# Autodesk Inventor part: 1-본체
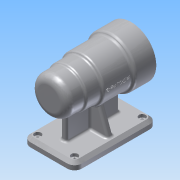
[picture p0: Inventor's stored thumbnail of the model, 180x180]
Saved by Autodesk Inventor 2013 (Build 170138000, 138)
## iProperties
Created: 2016-06
Part Number: 1-본체
Material: 알루미늄 6061
Document SubType Name: Modeling
Designer: Administrator
Density: 2.71 g/cm^3
Mass: 674.634 g
Surface Area: 646.752 cm^2
Volume: 248.942 cm^3
Author: Administrator
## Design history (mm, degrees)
sketch "스케치1"
  geometry: C1 r 25 at (0, 0); 1 further point
  constraints: 1 centre point, 1 coincident
  dimensions: "d0" = 50 diameter of C1
extrude "돌출1" new body sketch "스케치1" distance "d2" = 25; taper "d3" = 0 deg
sketch "스케치2"
  geometry: C1 r 25 at (0, 0) reference; C2 r 27 at (0, 0)
  constraints: 1 centre point, 1 coincident
  dimensions: "d4" = 54 diameter of C2
extrude "돌출2" join sketch "스케치2" distance "d6" = 20; taper "d7" = 0 deg
sketch "스케치3"
  geometry: C1 r 27 at (0, 0) reference; C2 r 30 at (0, 0)
  constraints: 1 centre point, 1 coincident
  dimensions: "d8" = 60 diameter of C2
extrude "돌출3" join sketch "스케치3" distance "d10" = 39; taper "d11" = 0 deg
sketch "스케치4"
  geometry: C1 r 30 at (0, 0) reference; C2 r 34 at (0, 0)
  constraints: 1 centre point, 1 coincident
  dimensions: "d12" = 68 diameter of C2
extrude "돌출4" join sketch "스케치4" distance "d14" = 28; taper "d15" = 0 deg
node "작업 평면1"
sketch "스케치5"
  geometry: L1 (-35, 25)-(35, 25); L2 (35, 25)-(35, -87); L3 (35, -87)-(-35, -87); L4 (-35, -87)-(-35, 25); L5 (25, 25)-(-25, 25) reference; L6 (-34, -87)-(34, -87) reference; 3 further points
  constraints: 8 end point, 2 midpoint, 2 parallel, 1 coincident, 1 horizontal, 1 horizontal alignment, 1 perpendicular
  dimensions: "d17" = 112 distance of L1.end L2.end; "d19" = 70 distance of L1.start L1.end
extrude "돌출5" join sketch "스케치5" distance "d20" = 10; taper "d21" = 0 deg
sketch "스케치6"
  geometry: L1 (-35, -25)-(35, -25) reference; L2 (35, 87)-(-35, 87) reference; L3 (-35, 87)-(-35, -25) reference; L4 (-4, -5)-(4, -5); L5 (4, -5)-(4, 67); L6 (4, 67)-(-4, 67); L7 (-4, 67)-(-4, -5); 5 further points
  constraints: 8 end point, 4 midpoint, 2 parallel, 1 horizontal, 1 horizontal alignment, 1 perpendicular, 1 vertical alignment
  dimensions: "d22" = 8 distance between parallel lines of L5 L7; "d24" = 20 distance between parallel lines of L2 L6
extrude "돌출6" join sketch "스케치6" stored distance "d25" = 10; taper "d26" = 0 deg
node "작업 평면2"
sketch "스케치7"
  geometry: L1 (39, 0)-(-31, 0) reference; L2 (-24, 0)-(-11.509, 34.32); L3 (-31, -10)-(-31, 0) reference; A1 r 30 centre (4, 60) between (8, 30.268) and (0, 30.268) reference; 1 further point
  constraints: 2 end point, 1 point on circle, 1 point on line
  dimensions: "d27" = 7 distance from line of L3 L2.start; "d29" = 110 deg angle of L2 L1
feature "리브1" sketch "스케치7" dims "d30" = 1, "d31" = 8, "d32" = 0, "d33" = 0, "d34" = 1, "d35" = 1
sketch "스케치8"
  geometry: L1 (39, 0)-(-31, 0) reference; L2 (32, 0)-(19.509, 34.32); L3 (39, -10)-(39, 0) reference; A1 r 30 centre (4, 60) between (8, 30.268) and (0, 30.268) reference; 1 further point
  constraints: 2 end point, 1 point on circle, 1 point on line
  dimensions: "d36" = 7 distance from line of L3 L2.start; "d37" = 110 deg angle of L1 L2
feature "리브2" sketch "스케치8" dims "d38" = 1, "d39" = 8, "d40" = 0, "d41" = 0, "d42" = 1, "d43" = 1
sketch "스케치9"
  geometry: C1 r 34 at (0, 0) reference; C2 r 21 at (0, 0)
  constraints: 1 centre point, 1 coincident
  dimensions: "d44" = 42 diameter of C2
extrude "돌출7" cut sketch "스케치9" distance "d46" = 15; taper "d47" = 0 deg
sketch "스케치10"
  geometry: C1 r 21 at (0, 0) reference; C2 r 24 at (0, 0)
  constraints: 1 centre point, 1 coincident
  dimensions: "d48" = 48 diameter of C2
extrude "돌출8" cut sketch "스케치10" distance "d50" = 54; taper "d51" = 0 deg
sketch "스케치11"
  geometry: C1 r 24 at (0, 0) reference; C2 r 21 at (0, 0)
  constraints: 1 centre point, 1 coincident
  dimensions: "d52" = 42 diameter of C2
extrude "돌출9" cut sketch "스케치11" distance "d54" = 12; taper "d55" = 0 deg
sketch "스케치12"
  geometry: C1 r 21 at (0, 0) reference; C2 r 17.5 at (0, 0)
  constraints: 1 centre point, 1 coincident
  dimensions: "d56" = 35 diameter of C2
extrude "돌출10" cut sketch "스케치12" distance "d58" = 18; taper "d59" = 0 deg
sketch "스케치13"
  geometry: C1 r 17.5 at (0, 0) reference; C2 r 16 at (0, 0)
  constraints: 1 centre point, 1 coincident
  dimensions: "d60" = 32 diameter of C2
extrude "돌출11" cut sketch "스케치13" distance "d62" = 4; taper "d63" = 0 deg
sketch "스케치14"
  geometry: C1 r 16 at (0, 0) reference; C2 r 10.5 at (0, 0)
  constraints: 1 centre point, 1 coincident
  dimensions: "d64" = 21 diameter of C2
extrude "돌출12" cut sketch "스케치14" distance "d66" = 3; taper "d67" = 0 deg
fillet "모깎기1" dims "d68" = 10
fillet "모깎기2" dims "d69" = 3
fillet "모깎기3" dims "d70" = 3
fillet "모깎기4" dims "d71" = 10
chamfer "모따기1" distance "d72" = 4; stored, may be unused: second distance "d73" = 2, angle "d74" = 45 deg
sketch "스케치15"
  geometry: L1 (-31, -15)-(-31, 77) reference; L2 (25, -21)-(-25, -21) reference; C1 r 4.5 at (-25, -15); C2 r 4.5 at (25, -15); C3 r 4.5 at (-25, 77); C4 r 4.5 at (25, 77); 3 further points
  constraints: 4 centre point, 3 equal radius, 2 horizontal alignment, 2 midpoint, 2 vertical alignment
  dimensions: "d75" = 92 distance of C1.centre C3.centre; "d77" = 46 vertical distance of point (-31, 31) C3.centre; "d78" = 50 distance of C2.centre C1.centre; "d79" = 25 horizontal distance of point (0, -21) C2.centre; "d80" = 9 diameter of C3
extrude "돌출13" cut sketch "스케치15" distance "d81" = 4; taper "d82" = 0 deg
sketch "스케치16"
  geometry: C1 r 4.5 at (0, 0) reference; C2 r 2.5 at (0, 0); 1 further point
  constraints: 1 centre point, 1 coincident
  dimensions: "d83" = 5 diameter of C2
extrude "돌출14" cut sketch "스케치16" stored distance "d85" = 4; taper "d86" = 0 deg
sketch "스케치17"
  geometry: C1 r 4.5 at (0, 0) reference; C2 r 2.5 at (0, 0); 1 further point
  constraints: 1 centre point, 1 coincident
  dimensions: "d87" = 5 diameter of C2
extrude "돌출15" cut sketch "스케치17" distance "d89" = 7; taper "d90" = 0 deg
sketch "스케치18"
  geometry: C1 r 4.5 at (0, 0) reference; C2 r 2.5 at (0, 0); 1 further point
  constraints: 1 centre point, 1 coincident
  dimensions: "d91" = 5 diameter of C2
extrude "돌출16" cut sketch "스케치18" distance "d93" = 7; taper "d94" = 0 deg
sketch "스케치19"
  geometry: C1 r 4.5 at (0, 0) reference; C2 r 2.5 at (0, 0); 1 further point
  constraints: 1 centre point, 1 coincident
  dimensions: "d95" = 5 diameter of C2
extrude "돌출17" cut sketch "스케치19" distance "d97" = 7; taper "d98" = 0 deg
fillet "모깎기5" dims "d99" = 3
fillet "모깎기6" dims "d100" = 0.3
fillet "모깎기7" dims "d101" = 3
chamfer "모따기2" distance "d102" = 1; stored, may be unused: second distance "d103" = 2, angle "d104" = 45 deg
sketch "스케치20"
  geometry: C1 r 34 at (0, 0) reference; C2 r 22 at (0, 0) reference; A1 r 26 centre (0, 0) between (0, 26) and (-26, 0); 2 further points
  constraints: 4 point on circle, 2 horizontal alignment, 2 vertical alignment, 1 centre point, 1 coincident
  dimensions: "d105" = 52 diameter of A1
hole "구멍1" sketch "스케치20" at (0, 26), (-26, 0), (0, -26), (26, 0) diameter "d107" = 3.242; stored, may be unused: countersink angle "d111" = 90 deg, drill point angle "d113" = 118 deg; dims "d108" = 8, "d109" = 4, "d110" = 2, "d112" = 11
node "작업 평면3"
sketch "스케치21"
  geometry: L1 (-34, -67)-(34, -67) reference; 2 further points
  constraints: 1 vertical alignment, 1 other
  dimensions: "d114" = 48 distance from line of L1 point (0, -19)
feature "엠보싱1" sketch "스케치21" dims "d12" = 68, "d115" = 0.5, "d116" = 0
fillet "모깎기8" dims "d117" = 3
fillet "모깎기9" dims "d118" = 3
fillet "모깎기10" dims "d119" = 4
fillet "모깎기11" dims "d120" = 3
fillet "모깎기12" dims "d121" = 3
node "솔리드1"
